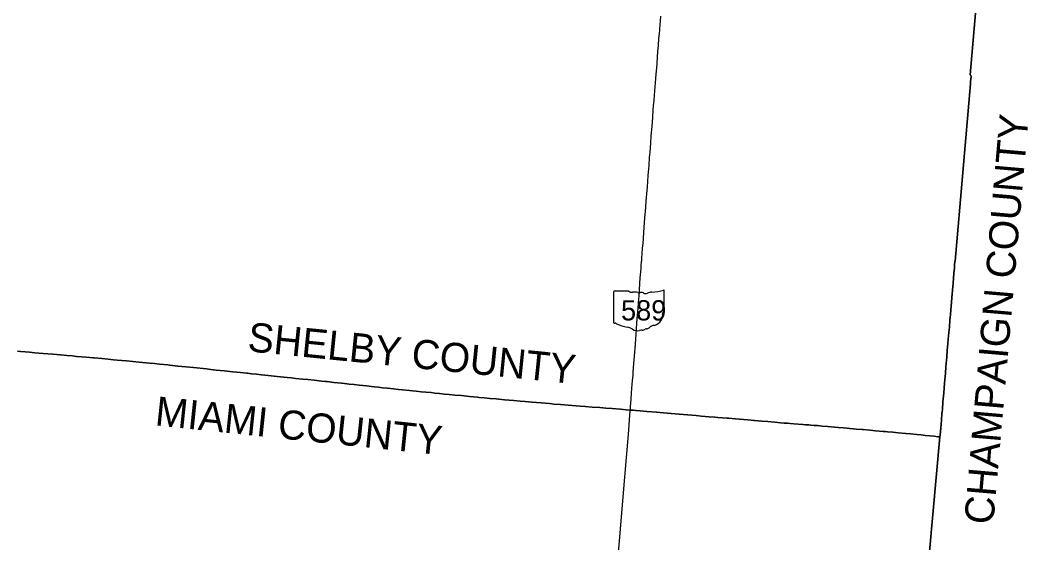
# Model space of a CAD drawing. Extents: x 0 to 34, y 0 to 22.
# Drawn here: x 5.598 to 6.154, y 17.581 to 17.87 of the extents above; entities that cross this region are included whole.
import ezdxf

# ---------------------------------------------------------------- set-up
doc = ezdxf.new("R2010")
doc.units = 0
for name, color, linetype in [('GM_X_County', 7, 'Continuous'), ('GM_X_County_Text', 7, 'Continuous'), ('GM_X_State_Location', 7, 'Continuous'), ('GM_X_State_Route', 7, 'Continuous'), ('GM_X_State_Shield', 7, 'Continuous')]:
    doc.layers.add(name, color=color, linetype=linetype)

msp = doc.modelspace()

# ---------------------------------------------------------------- linework, layer by layer
at = {"layer": 'GM_X_County'}
for points in [[(6.12823, 17.91011), (6.12222, 17.83973), (6.12237, 17.83959), (6.12246, 17.83946), (6.12253, 17.83932), (6.12258, 17.83912), (6.12262, 17.83886), (6.12262, 17.83865), (6.12261, 17.83833), (6.12254, 17.8377), (6.12245, 17.83702), (6.12237, 17.83639), (6.1223, 17.83576), (6.12225, 17.83524), (6.12225, 17.83503), (6.12227, 17.83488), (6.12231, 17.83478), (6.12237, 17.83468), (6.11381, 17.73693), (6.11373, 17.73676), (6.11368, 17.73655), (6.11365, 17.73635), (6.11361, 17.73591), (6.11357, 17.73544), (6.11354, 17.73498), (6.11349, 17.73419), (6.11341, 17.73309), (6.11319, 17.73041), (6.11292, 17.72725), (6.11275, 17.7251), (6.1127, 17.72461), (6.11257, 17.72316), (6.11234, 17.7207), (6.11217, 17.71881), (6.11201, 17.7169), (6.11179, 17.71401), (6.11149, 17.71007), (6.11123, 17.7072), (6.11098, 17.70451), (6.11065, 17.70055), (6.11037, 17.69747), (6.11004, 17.6939), (6.10982, 17.69122), (6.10952, 17.6877), (6.1092, 17.68392), (6.10906, 17.68234), (6.10875, 17.67866), (6.10844, 17.67509), (6.10798, 17.66947), (6.10775, 17.66673), (6.10755, 17.66426), (6.10712, 17.65917), (6.10678, 17.65507), (6.10658, 17.65265), (6.10628, 17.64934), (6.10604, 17.64667), (6.10586, 17.64483), (6.1055, 17.64079), (6.10541, 17.63989), (6.1042, 17.64001), (6.10231, 17.64022), (6.09979, 17.64047), (6.09738, 17.64074), (6.09505, 17.64096), (6.09269, 17.64118), (6.08912, 17.64152), (6.08659, 17.64179), (6.08245, 17.64219), (6.07937, 17.64248), (6.07644, 17.64274), (6.07523, 17.64284), (6.07414, 17.64294), (6.06988, 17.6433), (6.06687, 17.64354), (6.06314, 17.6439), (6.06261, 17.64395), (6.05929, 17.64423), (6.05411, 17.64471), (6.05232, 17.64487), (6.04928, 17.64514), (6.04744, 17.64529), (6.04365, 17.64561), (6.04039, 17.64589), (6.03781, 17.64611), (6.03601, 17.64625), (6.03425, 17.6464), (6.03315, 17.6465), (6.03146, 17.64661), (6.02989, 17.64672), (6.02731, 17.64694), (6.02482, 17.64713), (6.0228, 17.64727), (6.02127, 17.64741), (6.01984, 17.64753), (6.01954, 17.64756), (6.01739, 17.64773), (6.01437, 17.64796), (6.01055, 17.64831), (6.00724, 17.6486), (6.00309, 17.64895), (5.99941, 17.64925), (5.99489, 17.64964), (5.99269, 17.64982), (5.9888, 17.65016), (5.98811, 17.65022), (5.98538, 17.65045), (5.98281, 17.65068), (5.98128, 17.6508), (5.97818, 17.65106), (5.97372, 17.65143), (5.97093, 17.65167), (5.96624, 17.65206), (5.96398, 17.65224), (5.96158, 17.65247), (5.95928, 17.65264), (5.95296, 17.65318), (5.94902, 17.65352), (5.94371, 17.65395), (5.94003, 17.65426), (5.9377, 17.65445), (5.93625, 17.65458), (5.93467, 17.65471), (5.93457, 17.65471), (5.93239, 17.65489), (5.92915, 17.65515), (5.92467, 17.6555), (5.92106, 17.6558), (5.9177, 17.65606), (5.91359, 17.65639), (5.90965, 17.65669), (5.90692, 17.6569), (5.90027, 17.6574), (5.89612, 17.65774), (5.89241, 17.65805), (5.88994, 17.65826), (5.88548, 17.65867), (5.88026, 17.65909), (5.8766, 17.6594), (5.87374, 17.65965), (5.8704, 17.65996), (5.86509, 17.66042), (5.86058, 17.66086), (5.85717, 17.66115), (5.85391, 17.66148), (5.85122, 17.66172), (5.85029, 17.66181), (5.84579, 17.66224), (5.84148, 17.66266), (5.83772, 17.66302), (5.83464, 17.66332), (5.83214, 17.66357), (5.82935, 17.66385), (5.82678, 17.66412), (5.82468, 17.66433), (5.82179, 17.66461), (5.81927, 17.66486), (5.81649, 17.66513), (5.81439, 17.66535), (5.81282, 17.66551), (5.80883, 17.6659), (5.80676, 17.66612), (5.804, 17.66639), (5.8006, 17.66677), (5.79786, 17.66707), (5.79574, 17.6673), (5.79327, 17.66755), (5.78901, 17.66803), (5.78492, 17.66847), (5.7823, 17.66876), (5.77942, 17.66907), (5.77685, 17.66937), (5.77528, 17.66954), (5.77103, 17.66999), (5.76741, 17.67039), (5.76653, 17.67049), (5.76643, 17.6705), (5.76444, 17.67072), (5.76012, 17.67116), (5.75658, 17.67154), (5.75364, 17.67183), (5.74982, 17.67222), (5.74758, 17.67244), (5.74526, 17.67269), (5.73976, 17.67327), (5.73475, 17.6738), (5.73116, 17.67418), (5.72825, 17.67448), (5.72553, 17.67477), (5.72341, 17.675), (5.72299, 17.67505), (5.71943, 17.67541), (5.71515, 17.67583), (5.71067, 17.67632), (5.70831, 17.67658), (5.70608, 17.67682), (5.70305, 17.67716), (5.70075, 17.67741), (5.69361, 17.67816), (5.68927, 17.6786), (5.68501, 17.67902), (5.68047, 17.67948), (5.67938, 17.67959), (5.67483, 17.68004), (5.67201, 17.68032), (5.66928, 17.68059), (5.66366, 17.68113), (5.66004, 17.68148), (5.65653, 17.68182), (5.65154, 17.6823), (5.64949, 17.68249), (5.6465, 17.68277), (5.64299, 17.6831), (5.63867, 17.68349), (5.6382, 17.68353), (5.63636, 17.68369), (5.63437, 17.68386), (5.63185, 17.68409), (5.62896, 17.68436), (5.62675, 17.68455), (5.62365, 17.68481), (5.62024, 17.68512), (5.61588, 17.6855), (5.61067, 17.68593), (5.606, 17.68634), (5.60311, 17.6866), (5.60069, 17.68682), (5.59807, 17.68704), (5.59644, 17.68721)], [(6.09964, 17.57659), (6.10541, 17.63989), (6.1055, 17.64079), (6.10586, 17.64483), (6.10604, 17.64667), (6.10628, 17.64934), (6.10658, 17.65265), (6.10678, 17.65507), (6.10712, 17.65917), (6.10755, 17.66426), (6.10775, 17.66673), (6.10798, 17.66947), (6.10844, 17.67509), (6.10875, 17.67866), (6.10906, 17.68234), (6.1092, 17.68392), (6.10952, 17.6877), (6.10982, 17.69122), (6.11004, 17.6939), (6.11037, 17.69747), (6.11065, 17.70055), (6.11098, 17.70451), (6.11123, 17.7072), (6.11149, 17.71007), (6.11179, 17.71401), (6.11201, 17.7169), (6.11217, 17.71881), (6.11234, 17.7207), (6.11257, 17.72316), (6.1127, 17.72461), (6.11275, 17.7251), (6.11292, 17.72725), (6.11319, 17.73041), (6.11341, 17.73309), (6.11349, 17.73419), (6.11354, 17.73498), (6.11357, 17.73544), (6.11361, 17.73591), (6.11365, 17.73635), (6.11368, 17.73655), (6.11373, 17.73676), (6.11381, 17.73693), (6.12237, 17.83468), (6.12231, 17.83478), (6.12227, 17.83488), (6.12225, 17.83503), (6.12225, 17.83524), (6.1223, 17.83576), (6.12237, 17.83639), (6.12245, 17.83702), (6.12254, 17.8377), (6.12261, 17.83833), (6.12262, 17.83865), (6.12262, 17.83886), (6.12258, 17.83912), (6.12253, 17.83932), (6.12246, 17.83946), (6.12237, 17.83959), (6.12222, 17.83973), (6.12823, 17.91011)], [(5.59644, 17.68721), (5.59807, 17.68704), (5.60069, 17.68682), (5.60311, 17.6866), (5.606, 17.68634), (5.61067, 17.68593), (5.61588, 17.6855), (5.62024, 17.68512), (5.62365, 17.68481), (5.62675, 17.68455), (5.62896, 17.68436), (5.63185, 17.68409), (5.63437, 17.68386), (5.63636, 17.68369), (5.6382, 17.68353), (5.63867, 17.68349), (5.64299, 17.6831), (5.6465, 17.68277), (5.64949, 17.68249), (5.65154, 17.6823), (5.65653, 17.68182), (5.66004, 17.68148), (5.66366, 17.68113), (5.66928, 17.68059), (5.67201, 17.68032), (5.67483, 17.68004), (5.67938, 17.67959), (5.68047, 17.67948), (5.68501, 17.67902), (5.68927, 17.6786), (5.69361, 17.67816), (5.70075, 17.67741), (5.70305, 17.67716), (5.70608, 17.67682), (5.70831, 17.67658), (5.71067, 17.67632), (5.71515, 17.67583), (5.71943, 17.67541), (5.72299, 17.67505), (5.72341, 17.675), (5.72553, 17.67477), (5.72825, 17.67448), (5.73116, 17.67418), (5.73475, 17.6738), (5.73976, 17.67327), (5.74526, 17.67269), (5.74758, 17.67244), (5.74982, 17.67222), (5.75364, 17.67183), (5.75658, 17.67154), (5.76012, 17.67116), (5.76444, 17.67072), (5.76643, 17.6705), (5.76653, 17.67049), (5.76741, 17.67039), (5.77103, 17.66999), (5.77528, 17.66954), (5.77685, 17.66937), (5.77942, 17.66907), (5.7823, 17.66876), (5.78492, 17.66847), (5.78901, 17.66803), (5.79327, 17.66755), (5.79574, 17.6673), (5.79786, 17.66707), (5.8006, 17.66677), (5.804, 17.66639), (5.80676, 17.66612), (5.80883, 17.6659), (5.81282, 17.66551), (5.81439, 17.66535), (5.81649, 17.66513), (5.81927, 17.66486), (5.82179, 17.66461), (5.82468, 17.66433), (5.82678, 17.66412), (5.82935, 17.66385), (5.83214, 17.66357), (5.83464, 17.66332), (5.83772, 17.66302), (5.84148, 17.66266), (5.84579, 17.66224), (5.85029, 17.66181), (5.85122, 17.66172), (5.85391, 17.66148), (5.85717, 17.66115), (5.86058, 17.66086), (5.86509, 17.66042), (5.8704, 17.65996), (5.87374, 17.65965), (5.8766, 17.6594), (5.88026, 17.65909), (5.88548, 17.65867), (5.88994, 17.65826), (5.89241, 17.65805), (5.89612, 17.65774), (5.90027, 17.6574), (5.90692, 17.6569), (5.90965, 17.65669), (5.91359, 17.65639), (5.9177, 17.65606), (5.92106, 17.6558), (5.92467, 17.6555), (5.92915, 17.65515), (5.93239, 17.65489), (5.93457, 17.65471), (5.93467, 17.65471), (5.93625, 17.65458), (5.9377, 17.65445), (5.94003, 17.65426), (5.94371, 17.65395), (5.94902, 17.65352), (5.95296, 17.65318), (5.95928, 17.65264), (5.96158, 17.65247), (5.96398, 17.65224), (5.96624, 17.65206), (5.97093, 17.65167), (5.97372, 17.65143), (5.97818, 17.65106), (5.98128, 17.6508), (5.98281, 17.65068), (5.98538, 17.65045), (5.98811, 17.65022), (5.9888, 17.65016), (5.99269, 17.64982), (5.99489, 17.64964), (5.99941, 17.64925), (6.00309, 17.64895), (6.00724, 17.6486), (6.01055, 17.64831), (6.01437, 17.64796), (6.01739, 17.64773), (6.01954, 17.64756), (6.01984, 17.64753), (6.02127, 17.64741), (6.0228, 17.64727), (6.02482, 17.64713), (6.02731, 17.64694), (6.02989, 17.64672), (6.03146, 17.64661), (6.03315, 17.6465), (6.03425, 17.6464), (6.03601, 17.64625), (6.03781, 17.64611), (6.04039, 17.64589), (6.04365, 17.64561), (6.04744, 17.64529), (6.04928, 17.64514), (6.05232, 17.64487), (6.05411, 17.64471), (6.05929, 17.64423), (6.06261, 17.64395), (6.06314, 17.6439), (6.06687, 17.64354), (6.06988, 17.6433), (6.07414, 17.64294), (6.07523, 17.64284), (6.07644, 17.64274), (6.07937, 17.64248), (6.08245, 17.64219), (6.08659, 17.64179), (6.08912, 17.64152), (6.09269, 17.64118), (6.09505, 17.64096), (6.09738, 17.64074), (6.09979, 17.64047), (6.10231, 17.64022), (6.1042, 17.64001), (6.10541, 17.63989), (6.09964, 17.57659)]]:
    msp.add_lwpolyline(points, dxfattribs=at)
at = {"layer": 'GM_X_State_Route'}
for points in [[(5.93459, 17.65467), (5.93467, 17.65559), (5.93477, 17.65664), (5.9349, 17.65843), (5.93507, 17.6609), (5.93533, 17.66411), (5.93551, 17.66658), (5.93587, 17.67099), (5.9361, 17.67383), (5.93623, 17.67567), (5.93657, 17.68041), (5.93672, 17.6824), (5.93721, 17.68871), (5.93738, 17.69114), (5.93798, 17.69929), (5.93827, 17.70281), (5.93863, 17.70717), (5.93886, 17.7107), (5.93912, 17.71401), (5.9394, 17.71774), (5.93988, 17.72453), (5.94012, 17.72763), (5.94027, 17.72942), (5.94052, 17.73278), (5.94066, 17.73436), (5.94085, 17.73672), (5.94089, 17.73718), (5.94102, 17.73882), (5.94117, 17.74077), (5.94141, 17.74403), (5.94161, 17.74671), (5.94184, 17.7495), (5.9423, 17.7557), (5.9427, 17.76059), (5.94316, 17.76648), (5.94341, 17.76995), (5.94373, 17.774), (5.94402, 17.77789), (5.94425, 17.78089), (5.94451, 17.78415), (5.94492, 17.78967), (5.94528, 17.79403), (5.94549, 17.79703), (5.94588, 17.80192), (5.94618, 17.80608), (5.94657, 17.81112), (5.94698, 17.81622), (5.94728, 17.82032), (5.94748, 17.82264), (5.94773, 17.82579), (5.94815, 17.83094), (5.94848, 17.83531), (5.94886, 17.84004), (5.94918, 17.84366), (5.94936, 17.84603), (5.94964, 17.84944), (5.94987, 17.8526), (5.95014, 17.85591), (5.95043, 17.8598), (5.95065, 17.86238), (5.95081, 17.86448), (5.95087, 17.86518), (5.95102, 17.86727), (5.95122, 17.86937), (5.95147, 17.87215)], [(5.92759, 17.56964), (5.92871, 17.58257), (5.92997, 17.59776), (5.93093, 17.60906), (5.93252, 17.62861), (5.93353, 17.64122), (5.93442, 17.65194), (5.93457, 17.65413), (5.93458, 17.65434), (5.93459, 17.65467)]]:
    msp.add_lwpolyline(points, dxfattribs=at)
at = {"layer": 'GM_X_State_Shield'}
for p, q in [((5.92538, 17.71996), (5.92538, 17.70297)), ((5.93385, 17.72025), (5.92565, 17.72025)), ((5.95335, 17.71178), (5.95335, 17.72067)), ((5.95335, 17.71179), (5.95335, 17.71178))]:
    msp.add_line(p, q, dxfattribs=at)
for centre, major_axis, start_param, end_param in [((5.94339, 17.7434), (0.02966, 0), 4.814394, 5.042369), ((5.95304, 17.72071), (0.000311, 0), 6.141152, 7.989035), ((5.9257, 17.71999), (0.000324, 0), 1.712693, 3.28349), ((5.9358, 17.72222), (0.00314, 0), 4.042523, 4.731795), ((5.93684, 17.71071), (0.01128, 0), 1.404758, 1.657858), ((5.9394, 17.72008), (0.000907, 0), 3.836095, 5.185415), ((5.94073, 17.71812), (0.00189, 0), 0.950623, 2.079405), ((5.94316, 17.72081), (0.00227, 0), 4.081561, 5.145723), ((5.94717, 17.71506), (0.00597, 0), 1.699011, 2.107814), ((5.95328, 17.71113), (0.000482, 0), 1.883978, 3.671073), ((5.95021, 17.71001), (0.00289, 0), 5.934695, 6.695948), ((5.95302, 17.71175), (0.000333, 0), 5.05454, 6.418171), ((5.94505, 17.70694), (0.00742, 0), 5.101752, 6.440018), ((5.95447, 17.70807), (0.0021, 0), 2.387724, 3.262537), ((5.9257, 17.70293), (0.000327, 0), 3.00124, 4.508301), ((5.92575, 17.70467), (0.00249, 0), 4.665946, 4.897461), ((5.92626, 17.70199), (0.0009, 0), 0.519207, 1.627899), ((5.93762, 17.71725), (0.02142, 0), 4.195997, 4.488961), ((5.93123, 17.69534), (0.0067, 0), 0.823519, 1.323587), ((5.93848, 17.70191), (0.00425, 0), 4.026481, 4.996735), ((5.94094, 17.69604), (0.00349, 0), 1.495662, 1.94098), ((5.94125, 17.70064), (0.00227, 0), 4.691044, 5.507374), ((5.9433, 17.69899), (0.000638, 0), 1.147584, 2.315152), ((5.94303, 17.70133), (0.0024, 0), 4.937069, 5.64225), ((5.94818, 17.6982), (0.00406, 0), 1.647645, 2.488434)]:
    msp.add_ellipse(centre, major_axis=major_axis, ratio=0.8, start_param=start_param, end_param=end_param, dxfattribs=at)

# ---------------------------------------------------------------- texts
at = {"layer": 'GM_X_County_Text'}
for s, rotation, p in [('CHAMPAIGN COUNTY', 85.032, (6.13484, 17.59119)), ('SHELBY COUNTY', 354.261, (5.723, 17.68722)), ('MIAMI COUNTY', 354.0434, (5.67192, 17.64632))]:
    msp.add_text(s, height=0.016074, rotation=rotation, dxfattribs=at).set_placement(p)
at = {"layer": 'GM_X_State_Location'}
for s in ['s', 'r']:
    msp.add_text(s, height=0.0000161, dxfattribs=at).set_placement((5.93905, 17.71034))
msp.add_text('589', height=0.0000161, rotation=0, dxfattribs=at).set_placement((5.93338, 17.70917))
at = {"layer": 'GM_X_State_Shield'}
msp.add_text('589', height=0.011189, dxfattribs=at).set_placement((5.92949, 17.70417))

doc.saveas('drawing.dxf')
